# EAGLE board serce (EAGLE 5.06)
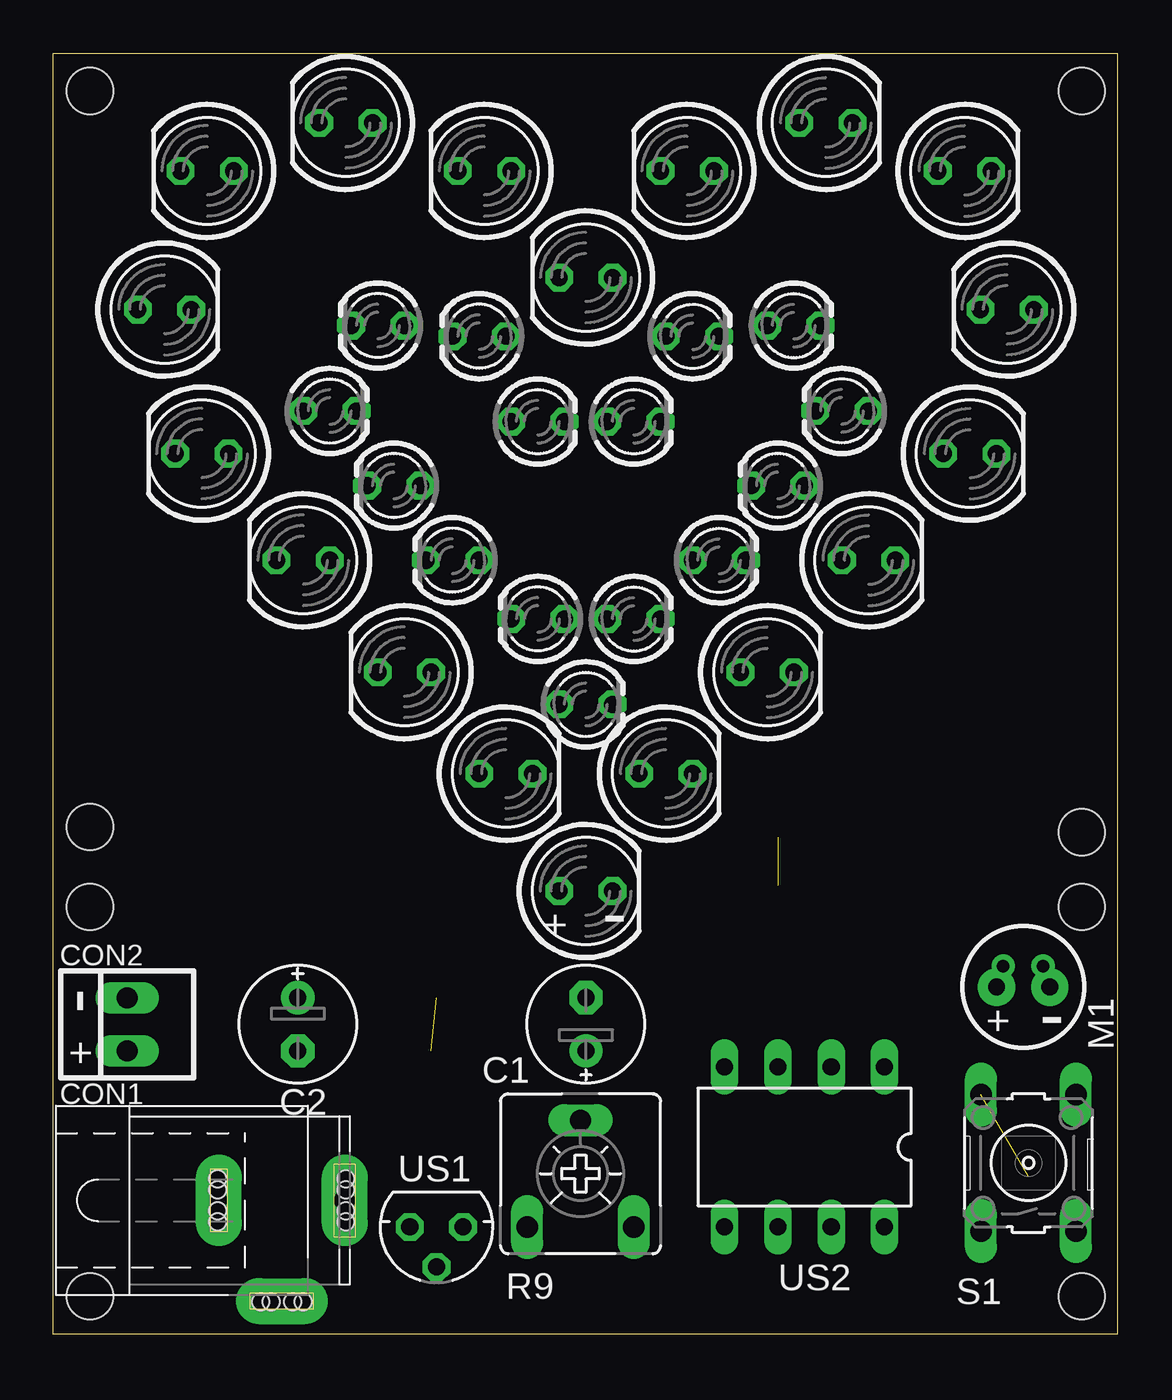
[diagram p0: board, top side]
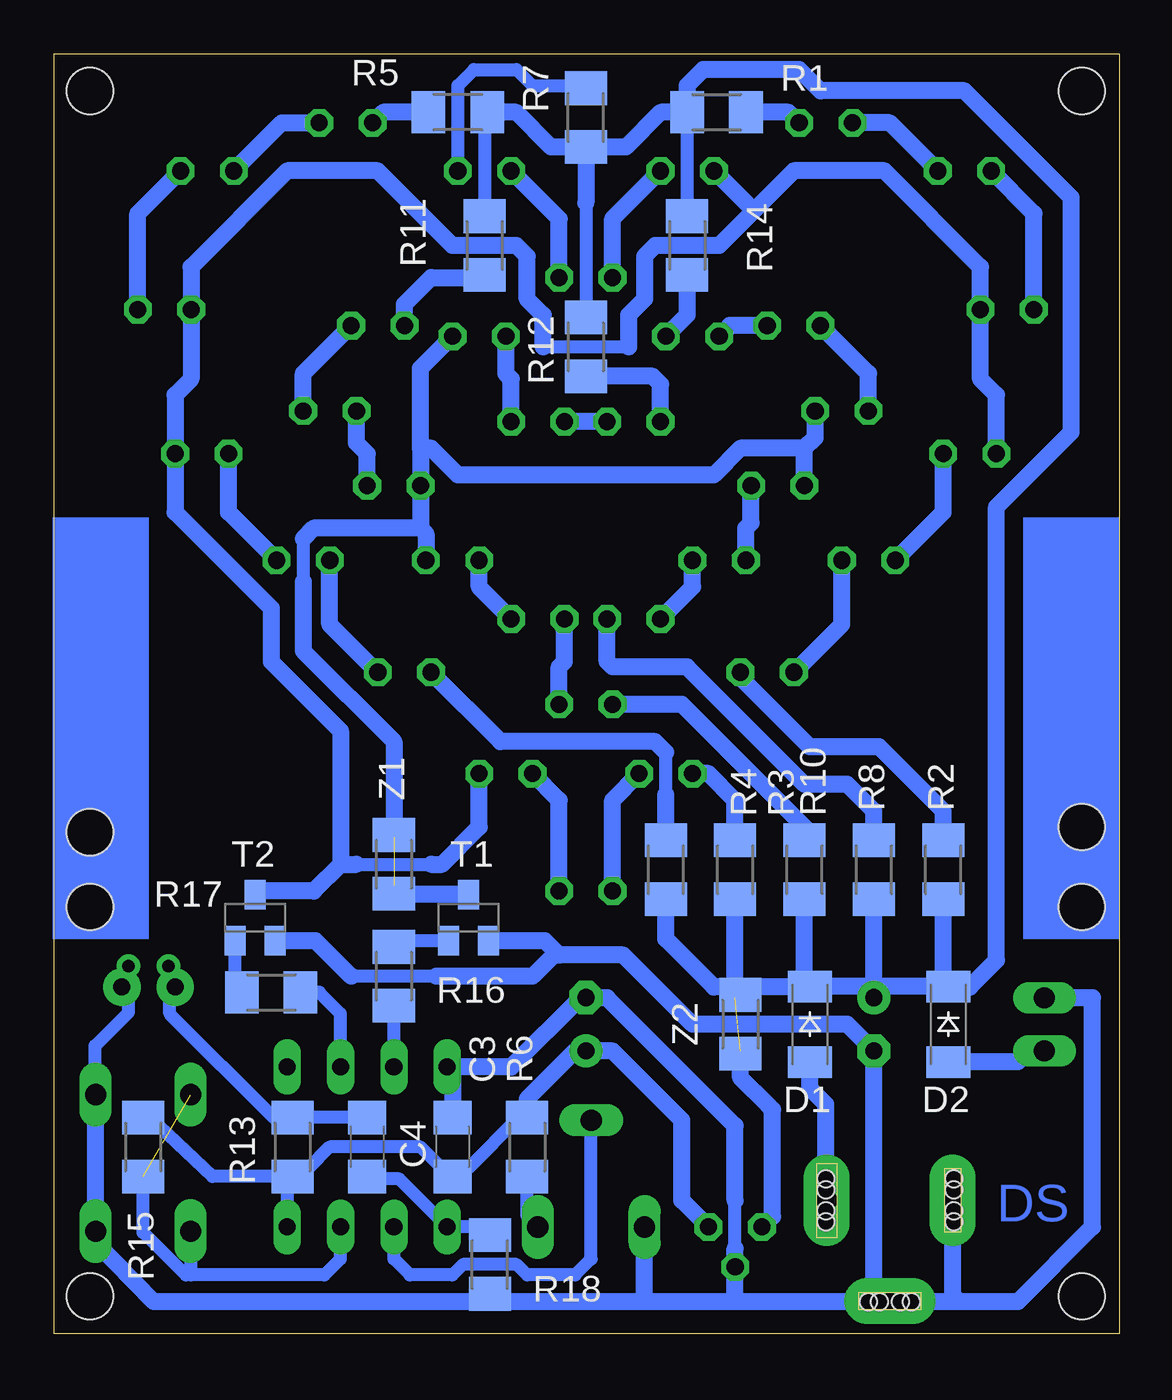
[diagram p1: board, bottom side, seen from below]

Size 50.72 x 60.97 mm. Coordinates in mm from the lower left corner, seen from the top.
Outline: 0,0.01 50.72,0.01 50.72,60.96 0,60.97 0,0
Copper layers (1*16): Top 0.035mm / dielectric 1.5mm / Bottom 0.035mm
Design rules "default": minimum track width 10mil, minimum drill 24mil, track to track 8mil, track to pad 8mil, pad to pad 8mil, via to via 8mil, smd to smd 8mil, copper to edge 40mil, drill to drill 8mil, minimum pad ring 10mil, minimum via ring 8mil, stop-mask expansion 4mil, vias tented up to drill 0mil, thermal gap 10mil
Holes 2.2 mm at 49.02,1.79 1.78,1.79 49.02,20.33 1.78,20.33 49.02,59.19 1.78,59.19 1.78,24.14 49.02,23.89
Holes 0.8 mm at 13.97,6.87 13.97,7.38 13.97,5.85 13.97,5.34 11.43,1.53 11.94,1.53 10.41,1.53 9.91,1.53 7.87,5.85 7.87,5.34 7.87,6.87 7.87,7.38

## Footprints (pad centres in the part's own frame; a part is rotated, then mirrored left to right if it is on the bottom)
E2,5-6E = drill 0.813 pad 1.575 round: + -1.27,0 | drill 0.813 pad 1.575 octagon: - 1.27,0
C1206 = smd 1.6 x 1.8: 1 -1.4,0; 2 1.4,0
SPC4077 = drill 0.8 pad 2.184 long: 1 -3,0; 2 0,-4.8 | drill 1 pad 2.184 long: 3 3,0
22-23-2021 = drill 1 long: 1 -1.27,0; 2 1.27,0
SOD-123_MINI-SMA = smd 1.5 x 2.1: A 1.8,0; C -1.8,0
LED5MM = drill 0.813 octagon: A -1.27,0; K 1.27,0
LED3MM = drill 0.813 octagon: A -1.27,0; K 1.27,0
WM-62PC/62PK = drill 0.6 pad 1 round: 1 -1,0.95; 2 -1,-0.95
M1206 = smd 1.6 x 2: 1 -1.4,0; 2 1.4,0
CA6V = drill 1.016 long: A -2.54,-2.54; E 2.54,-2.54; S 0,2.54
B3F-10XX = drill 1.016 long: 1 -3.251,2.261; 2 3.251,2.261; 3 -3.251,-2.261; 4 3.251,-2.261
SOT23-BEC = smd 1 x 1.4: B -0.95,-1.1; C 0,1.1; E 0.95,-1.1
78LXX = drill 0.813 octagon: GND 0,1.905; IN 1.27,0; OUT -1.27,0
DIL08 = drill 0.813 long: 1 -3.81,-3.81; 2 -1.27,-3.81; 3 1.27,-3.81; 4 3.81,-3.81; 5 3.81,3.81; 6 1.27,3.81; 7 -1.27,3.81; 8 -3.81,3.81

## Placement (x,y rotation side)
C1  100uF  [E2,5-6E]  25.4,14.74 90 top
C2  100uF  [E2,5-6E]  11.68,14.74 270 top
C3  1uF  [C1206]  31.75,8.9 270 bottom
C4  1uF  [C1206]  35.81,8.9 270 bottom
CON1  [SPC4077]  10.92,6.36 0 top
CON2  [22-23-2021]  3.56,14.74 90 top
D1  BAS85  [SOD-123_MINI-SMA]  14.73,14.74 270 bottom
D2  BAS85  [SOD-123_MINI-SMA]  8.13,14.74 270 bottom
LED1  [LED5MM]  5.33,48.78 0 top
LED2  [LED5MM]  7.37,55.38 180 top
LED3  [LED5MM]  13.97,57.67 180 top
LED4  [LED5MM]  7.11,41.92 180 top
LED5  [LED5MM]  11.94,36.84 180 top
LED6  [LED5MM]  16.76,31.51 180 top
LED7  [LED5MM]  29.21,26.68 0 top
LED8  [LED5MM]  25.4,21.09 0 top
LED9  [LED5MM]  21.59,26.68 0 top
LED10  [LED5MM]  43.69,41.92 0 top
LED11  [LED5MM]  38.86,36.84 0 top
LED12  [LED5MM]  34.04,31.51 0 top
LED13  [LED5MM]  45.47,48.78 180 top
LED14  [LED5MM]  43.43,55.38 0 top
LED15  [LED5MM]  36.83,57.67 0 top
LED16  [LED5MM]  20.57,55.38 180 top
LED17  [LED5MM]  25.4,50.3 180 top
LED18  [LED5MM]  30.23,55.38 180 top
LED19  [LED3MM]  16.26,40.4 180 top
LED20  [LED3MM]  19.05,36.84 180 top
LED21  [LED3MM]  23.11,34.05 180 top
LED22  [LED3MM]  31.75,36.84 0 top
LED23  [LED3MM]  27.69,34.05 0 top
LED24  [LED3MM]  25.4,29.98 0 top
LED25  [LED3MM]  34.54,40.4 180 top
LED26  [LED3MM]  37.59,43.95 180 top
LED27  [LED3MM]  35.31,48.02 0 top
LED28  [LED3MM]  30.48,47.51 0 top
LED29  [LED3MM]  27.69,43.44 0 top
LED30  [LED3MM]  23.11,43.44 0 top
LED31  [LED3MM]  13.21,43.95 0 top
LED32  [LED3MM]  15.49,48.02 180 top
LED33  [LED3MM]  20.32,47.51 180 top
M1  MIC1  [WM-62PC/62PK]  46.23,16.52 270 top
R1  [M1206]  19.18,58.18 180 bottom
R2  [M1206]  8.38,22.11 270 bottom
R3  [M1206]  18.29,22.11 270 bottom
R4  [M1206]  21.59,22.11 270 bottom
R5  [M1206]  31.5,58.18 0 bottom
R6  22k  [M1206]  28.19,8.9 90 bottom
R7  [M1206]  25.4,57.92 270 bottom
R8  [M1206]  11.68,22.11 270 bottom
R9  4k7  [CA6V]  25.15,7.63 0 top
R10  [M1206]  14.99,22.11 270 bottom
R11  [M1206]  30.23,51.83 90 bottom
R12  [M1206]  25.4,47 90 bottom
R13  10k  [M1206]  39.37,8.9 90 bottom
R14  [M1206]  20.57,51.83 90 bottom
R15  10k  [M1206]  46.48,8.9 90 bottom
R16  10k  [M1206]  34.54,17.03 90 bottom
R17  10k  [M1206]  40.39,16.27 180 bottom
R18  10k  [M1206]  29.97,3.31 270 bottom
S1  [B3F-10XX]  46.48,8.14 90 top
T1  BC517  [SOT23-BEC]  30.99,19.82 0 bottom
T2  BC517  [SOT23-BEC]  41.15,19.82 0 bottom
US1  78L05  [78LXX]  18.29,5.09 180 top
US2  ATTINY13  [DIL08]  35.81,8.9 180 top
Z1  [M1206]  34.54,22.36 90 bottom
Z2  [M1206]  18.03,14.74 90 bottom

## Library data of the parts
C1-C4 R1-R8 R10-R18 Z1 Z2 = rcl
CON1 = con-jack
CON2 = con-molex
D1 D2 = diode
LED1-LED33 = led
M1 = microphon
R9 = pot
S1 = switch-omron
T1 T2 = transistor-npn
US1 = v-reg
US2 = atmel

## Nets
GND: C1.- C2.- C3.1 CON1.1 CON1.2 CON2.2 M1.1 R9.A R18.2 S1.3 S1.4 T1.E T2.E US1.GND US2.4
L1: LED1.K LED4.K LED7.K LED10.K LED13.K LED16.K T2.C
L2: LED19.K LED22.K LED25.K LED28.K LED31.K T1.C
MIC: C4.2 R18.1 US2.5
N$2: LED1.A LED2.K
N$3: LED2.A LED3.K
N$4: LED28.A LED29.K
N$5: CON1.3 D1.A
N$6: LED25.A LED26.K
N$7: CON2.1 D2.A
N$8: LED3.A R1.1
N$9: LED31.A LED32.K
N$10: LED22.A LED23.K
N$11: C4.1 M1.2 R13.2
N$12: R17.2 T2.B
N$13: R16.2 T1.B
N$14: LED19.A LED20.K
N$15: LED16.A LED17.K
N$16: R6.1 R9.E
N$17: LED13.A LED14.K
N$18: LED10.A LED11.K
N$19: LED7.A LED8.K
N$20: LED4.A LED5.K
N$21: LED29.A LED30.K
N$22: LED26.A LED27.K
N$23: LED23.A LED24.K
N$24: LED20.A LED21.K
N$25: LED17.A LED18.K
N$26: LED14.A LED15.K
N$27: LED11.A LED12.K
N$28: LED8.A LED9.K
N$29: LED5.A LED6.K
N$30: LED30.A R12.1
N$31: LED27.A R11.1
N$32: LED24.A R10.1
N$33: LED21.A R8.1
N$34: LED18.A R7.1
N$35: LED15.A R5.1
N$36: LED12.A R4.1
N$37: LED9.A R3.1
N$38: LED6.A R2.1
N$39: LED32.A LED33.K
N$40: LED33.A R14.1
OUT1: R16.1 US2.3
OUT2: R17.1 US2.2
REG: R9.S US2.6
SW: R15.1 S1.1 S1.2 US2.7
VCC: C1.+ C3.2 R6.2 R13.1 R15.2 US1.OUT US2.8
VDD: C2.+ D1.C D2.C R1.2 R2.2 R3.2 R4.2 R5.2 R7.2 R8.2 R10.2 R11.2 R12.2 R14.2 US1.IN

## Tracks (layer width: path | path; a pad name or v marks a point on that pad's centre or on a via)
GND
  Bottom 0.61: 18.29,4.07 18.29,6.36 | M1.1 47.18,15.32 48.77,13.73 48.77,11.41 S1.4 | 32.51,17.03 36.58,17.03
  Bottom 0.813: CON2.2 1.27,16.01 1.27,5.09 4.83,1.53 7.62,1.53 | 7.62,1.53 10.9,1.53 | 10.9,1.53 CON1.2 | CON1.1 7.92,1.84 7.62,1.53 | 10.9,1.53 11.43,1.53 | 11.43,1.53 18.29,1.53 | 18.29,1.53 22.86,1.53 | 18.29,1.53 US1.GND 18.29,4.07 | R9.A 22.61,1.79 22.86,1.53 | 22.86,1.53 30.23,1.53 | 30.23,1.53 45.97,1.53 48.74,4.35 S1.3 S1.4 | 11.43,1.53 11.68,1.79 C2.- 12.95,14.74 20.32,14.74 23.62,18.04 26.67,18.04 | 18.29,6.36 18.29,9.92 24.38,16.01 C1.- 25.65,16.01 28.96,12.71 31.75,12.71 | 31.75,12.71 C3.1 | 31.75,12.71 US2.4 | T2.E 38.27,18.72 36.58,17.03 | 32.51,17.03 27.94,17.03 26.92,18.04 26.67,18.04 | T1.E 27.35,18.72 26.67,18.04 | R18.2 29.97,1.79 30.23,1.53
L1
  Bottom 0.61: 36.32,22.36 32.77,22.36 | 23.37,47 27.43,47
  Bottom 0.813: LED4.K 5.84,44.71 6.6,45.48 LED1.K 6.6,50.81 11.18,55.38 15.49,55.38 17.4,53.48 | 37.08,22.36 36.32,22.36 | 37.08,22.36 38.35,21.09 40.98,21.09 T2.C | 27.43,47 27.43,48.52 28.19,49.29 28.19,51.32 28.7,51.83 31.75,51.83 35.31,55.38 39.62,55.38 44.2,50.81 LED13.K 44.2,45.48 44.96,44.71 LED10.K 44.96,39.13 40.39,34.55 40.39,32.01 37.08,28.71 37.08,22.36 | 23.37,47 23.37,48.52 22.61,49.29 22.61,51.32 22.1,51.83 19.05,51.83 17.4,53.48 | 17.4,53.48 LED16.K | LED7.K 30.48,24.14 32.26,22.36 32.77,22.36
L2  (1 unrouted)
  Bottom 0.61: 38.86,37.86 38.86,35.82
  Bottom 0.813: 33.27,42.17 LED25.K 33.27,38.36 | 33.27,42.17 33.27,45.98 LED28.K | LED19.K 14.99,42.17 | 14.99,42.17 14.48,42.68 LED31.K | 14.99,42.17 18.03,42.17 19.3,40.9 31.5,40.9 32.77,42.17 33.27,42.17 | 38.86,37.86 38.35,38.36 33.27,38.36 | T1.C 34.12,20.92 34.54,21.35 | 34.54,23.63 34.54,28.2 38.86,32.52 38.86,35.82 | LED22.K 33.02,38.11 33.27,38.36
MIC
  Bottom 0.61: R18.1 30.35,5.09 US2.5 34.29,7.38 35.18,7.38 C4.2
N$1  (via drill 0.8 pad 1.78)
  other vias: 47.5,16.52
N$2
  Bottom 0.813: LED1.A 4.06,53.35 LED2.K
N$3
  Bottom 0.813: LED2.A 10.92,57.67 LED3.K
N$4
  Bottom 0.813: LED28.A 29.21,45.73 28.96,45.48 LED29.K
N$5
  Bottom 0.813: D1.A 14.73,11.69 13.97,10.93 13.97,6.41 CON1.3
N$6
  Bottom 0.813: LED25.A 35.81,41.92 36.32,42.43 LED26.K
N$7
  Bottom 0.813: CON2.1 4.32,13.47 4.83,12.96 8.11,12.96 D2.A
N$8
  Bottom 0.813: R1.1 15.75,58.18 LED3.A
N$9
  Bottom 0.813: LED31.A 11.94,45.73 LED32.K
N$10
  Bottom 0.813: LED22.A 30.48,35.57 LED23.K
N$11
  Bottom 0.61: C4.1 R13.2 40.26,10.3 45.21,15.25 45.21,17.45 M1.2
N$12
  Bottom 0.61: T2.B 42.1,16.46 R17.2
N$13
  Bottom 0.61: T1.B 34.25,18.72 R16.2
N$14
  Bottom 0.813: LED19.A 17.53,38.62 17.78,38.36 LED20.K
N$15
  Bottom 0.813: LED16.A 24.13,53.1 LED17.K
N$16
  Bottom 0.61: R6.1 28.19,5.6 R9.E
N$17
  Bottom 0.813: LED14.K 46.74,53.35 LED13.A
N$18
  Bottom 0.813: LED11.K 42.42,39.13 LED10.A
N$19
  Bottom 0.813: LED8.K 26.67,25.41 LED7.A
N$20
  Bottom 0.813: LED4.A 8.38,39.13 LED5.K
N$21
  Bottom 0.813: LED30.K LED29.A
N$22
  Bottom 0.813: LED26.A 38.86,45.73 LED27.K
N$23
  Bottom 0.813: LED24.K 26.67,31.76 26.42,32.01 LED23.A
N$24
  Bottom 0.813: LED20.A 20.32,35.57 LED21.K
N$25
  Bottom 0.813: LED18.K 26.67,53.1 LED17.A
N$26
  Bottom 0.813: LED15.K 39.88,57.67 LED14.A
N$27
  Bottom 0.813: LED12.K 37.59,33.79 LED11.A
N$28
  Bottom 0.813: LED8.A 24.13,25.41 LED9.K
N$29
  Bottom 0.813: LED5.A 13.21,33.79 LED6.K
N$30
  Bottom 0.813: R12.1 22.22,45.6 21.84,45.22 LED30.A
N$31
  Bottom 0.813: LED27.A 34.04,49.03 32.77,50.3 30.35,50.3 R11.1
N$32
  Bottom 0.813: LED24.A 20.83,29.98 14.99,24.14 R10.1
N$33
  Bottom 0.813: LED21.A 24.38,32.01 24.13,31.76 20.57,31.76 14.99,26.17 12.95,26.17 11.68,24.9 R8.1
N$34
  Bottom 0.61: LED18.A 31.5,59.45 30.73,60.21 28.7,60.21 27.94,59.45 25.52,59.45 R7.1
N$35
  Bottom 0.813: R5.1 35.05,58.18 LED15.A
N$36
  Bottom 0.61: 21.59,25.66 21.59,27.7
  Bottom 0.813: LED12.A 29.46,28.2 22.1,28.2 21.59,27.7 | R4.1 21.59,25.66
N$37
  Bottom 0.813: LED9.A 19.56,26.68 18.29,25.41 R3.1
N$38
  Bottom 0.813: LED6.A 18.03,31.25 14.73,27.95 11.43,27.95 8.38,24.9 R2.1
N$39
  Bottom 0.813: LED32.A 18.54,48.02 LED33.K
N$40
  Bottom 0.813: R14.1 20.57,48.52 LED33.A
N$41  (via drill 0.8 pad 1.78)
  other vias: 44.96,16.52
OUT1
  Bottom 0.61: 34.54,15.88 R16.1 US2.3
OUT2
  Bottom 0.61: R17.1 38.1,16.27 37.08,15.25 US2.2
REG
  Bottom 0.61: US2.6 34.54,3.57 33.78,2.8 31.75,2.8 31.24,3.31 28.7,3.31 28.19,2.8 25.91,2.8 25.15,3.57 R9.S
SW  (1 unrouted)
  Bottom 0.61: US2.7 37.08,3.57 37.85,2.8 44.2,2.8 | 44.2,2.8 44.2,4.35 S1.1 | R15.1 46.48,4.84 44.45,2.8 44.2,2.8
VCC
  Bottom 0.61: 28.19,11.19 R6.2 28.57,10.3 30.99,7.88 31.11,7.88 C3.2 31.87,7.5 33.27,8.9 37.59,8.9 38.61,7.88 38.99,7.88 R13.1 | R15.2 46.1,10.3 45.72,9.92 43.17,7.5 R13.1 | US2.8 39.62,7.25 R13.1
  Bottom 0.813: 28.19,11.19 25.91,13.47 C1.+ 24.13,13.47 20.83,10.17 20.83,6.36 US1.OUT
VDD  (1 unrouted)
  Bottom 0.61: 25.4,53.86 R12.2 | R14.2 R1.2 | R11.2 30.23,58.05 R5.2
  Bottom 0.813: D2.C 11.68,16.54 | 11.68,16.54 D1.C 15.26,16.52 | 11.68,16.54 C2.+ | R7.2 27.05,56.52 28.7,58.18 R5.2 | R7.2 23.5,56.52 21.84,58.18 R1.2 20.58,59.44 19.81,60.21 15.24,60.21 14.22,59.19 7.37,59.19 2.29,54.11 2.29,42.94 5.84,39.38 5.84,17.79 7.11,16.52 8.11,16.52 D2.C | R7.2 25.4,53.86 | R2.2 8.38,16.8 D2.C | 11.68,16.54 R8.2 | R10.2 14.99,16.8 15.26,16.52 | R4.2 21.59,18.81 19.3,16.52 18.29,16.52 | 15.26,16.52 18.29,16.52 | 18.29,16.52 R3.2 | US1.IN 16.51,5.6 16.51,10.68 16.76,10.93 18.03,12.2 18.03,13.47 | 18.29,16.52 18.29,16.01
(copper drawn outside any net)
  shapes: Bottom area x2

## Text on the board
Bottom: DS
tPlace: + | - | - | + | - | +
